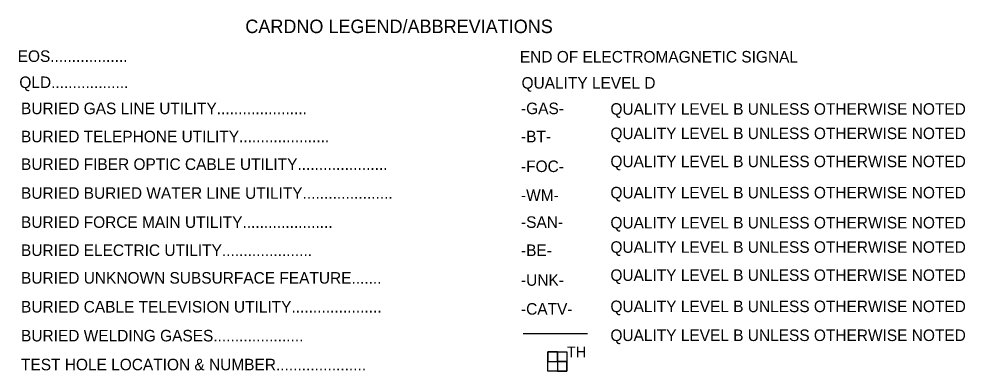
# Model space of a CAD drawing. Extents: x 1797765 to 1816938, y 246120 to 250965.
# Drawn here: x 1805745 to 1806237, y 250781.9 to 250965.2 of the extents above; entities that cross this region are included whole.
import ezdxf

# ---------------------------------------------------------------- set-up
doc = ezdxf.new("R2010")
doc.units = 0
for name, color, linetype in [('EX-UGUT-ELEC-X-CARDNO-X', 7, 'Continuous'), ('EX-UGUT-FOC-X-CARDNO-X', 7, 'Continuous'), ('EX-UGUT-GAS_MAIN-X-CARDNO-X', 7, 'Continuous'), ('EX-UGUT-SANSW-X-CARDNO-X', 7, 'Continuous'), ('EX-UGUT-TELE-X-CARDNO-X', 7, 'Continuous'), ('EX-UGUT-TV-X-CARDNO_X', 7, 'Continuous'), ('EX-UGUT-TXT', 7, 'Continuous'), ('EX-UGUT-WATER-X-CARDNO-X', 7, 'Continuous'), ('EX-UGUT-WEILDING_GAS-X-CARDNO-X', 7, 'Continuous'), ('EX-UGUT-X-CARDNO-X', 7, 'Continuous'), ('SU_QLATestHole_ep', 7, 'Continuous'), ('UGUT-TXT', 7, 'Continuous')]:
    doc.layers.add(name, color=color, linetype=linetype)

msp = doc.modelspace()

# ---------------------------------------------------------------- linework, layer by layer
at = {"layer": 'EX-UGUT-WEILDING_GAS-X-CARDNO-X'}
msp.add_line((1806040.75, 250801.26), (1806007.29, 250801.26), dxfattribs=at)
at = {"layer": 'SU_QLATestHole_ep'}
for p, q in [((1806020.01, 250791.9), (1806030.01, 250791.9)), ((1806020.01, 250781.9), (1806020.01, 250791.9)), ((1806020.01, 250791.9), (1806020.01, 250786.9)), ((1806025.01, 250791.9), (1806020.01, 250791.9)), ((1806025.01, 250791.9), (1806025.01, 250781.9)), ((1806025.01, 250786.9), (1806025.01, 250791.9)), ((1806030.01, 250791.9), (1806030.01, 250781.9)), ((1806020.01, 250786.9), (1806030.01, 250786.9)), ((1806020.01, 250786.9), (1806025.01, 250786.9)), ((1806030.01, 250786.9), (1806025.01, 250786.9)), ((1806025.01, 250786.9), (1806025.01, 250781.9)), ((1806030.01, 250781.9), (1806030.01, 250786.9)), ((1806030.01, 250781.9), (1806020.01, 250781.9)), ((1806025.01, 250781.9), (1806030.01, 250781.9))]:
    msp.add_line(p, q, dxfattribs=at)

# ---------------------------------------------------------------- texts
at = {"layer": 'EX-UGUT-ELEC-X-CARDNO-X'}
msp.add_text('-BE-', height=6.007, dxfattribs=at).set_placement((1806006.12, 250841.81))
at = {"layer": 'EX-UGUT-FOC-X-CARDNO-X'}
msp.add_text('-FOC-', height=6.007, dxfattribs=at).set_placement((1806006.12, 250885.5))
at = {"layer": 'EX-UGUT-GAS_MAIN-X-CARDNO-X'}
msp.add_text('-GAS-', height=6.007, dxfattribs=at).set_placement((1806006.12, 250915.63))
at = {"layer": 'EX-UGUT-SANSW-X-CARDNO-X'}
msp.add_text('-SAN-', height=6.007, dxfattribs=at).set_placement((1806006.12, 250856.44))
at = {"layer": 'EX-UGUT-TELE-X-CARDNO-X'}
msp.add_text('-BT-', height=6.007, dxfattribs=at).set_placement((1806006.12, 250901))
at = {"layer": 'EX-UGUT-TV-X-CARDNO_X'}
msp.add_text('-CATV-', height=6.007, dxfattribs=at).set_placement((1806006.12, 250811.27))
at = {"layer": 'EX-UGUT-TXT'}
for s, p in [('EOS..................', (1805744.38, 250942.82)), ('END OF ELECTROMAGNETIC SIGNAL', (1806005.53, 250942.52)), ('QLD..................', (1805745.25, 250929.23)), ('QUALITY LEVEL D ', (1806006.4, 250928.92)), ('BURIED GAS LINE UTILITY.....................', (1805746.13, 250915.63)), ('QUALITY LEVEL B UNLESS OTHERWISE NOTED', (1806052.61, 250915.33)), ('QUALITY LEVEL B UNLESS OTHERWISE NOTED', (1806052.61, 250902.65)), ('BURIED TELEPHONE UTILITY.....................', (1805746.13, 250901)), ('QUALITY LEVEL B UNLESS OTHERWISE NOTED', (1806052.61, 250888.03)), ('BURIED FIBER OPTIC CABLE UTILITY.....................', (1805746.13, 250886.61)), ('BURIED BURIED WATER LINE UTILITY.....................', (1805746.13, 250871.58)), ('QUALITY LEVEL B UNLESS OTHERWISE NOTED', (1806052.61, 250871.78)), ('BURIED FORCE MAIN UTILITY.....................', (1805746.13, 250856.44)), ('QUALITY LEVEL B UNLESS OTHERWISE NOTED', (1806052.61, 250856.14)), ('QUALITY LEVEL B UNLESS OTHERWISE NOTED', (1806052.61, 250843.46)), ('BURIED ELECTRIC UTILITY.....................', (1805746.13, 250841.81)), ('QUALITY LEVEL B UNLESS OTHERWISE NOTED', (1806052.61, 250828.84)), ('BURIED UNKNOWN SUBSURFACE FEATURE.......', (1805746.13, 250827.42)), ('BURIED CABLE TELEVISION UTILITY.....................', (1805746.13, 250812.39)), ('QUALITY LEVEL B UNLESS OTHERWISE NOTED', (1806052.61, 250812.59)), ('BURIED WELDING GASES.....................', (1805746.13, 250797.35)), ('QUALITY LEVEL B UNLESS OTHERWISE NOTED', (1806052.61, 250797.55)), ('TEST HOLE LOCATION & NUMBER.....................', (1805746.13, 250782.31))]:
    msp.add_text(s, height=6.0075, dxfattribs=at).set_placement(p)
at = {"layer": 'EX-UGUT-WATER-X-CARDNO-X'}
msp.add_text('-WM-', height=6.007, dxfattribs=at).set_placement((1806006.12, 250870.46))
at = {"layer": 'EX-UGUT-X-CARDNO-X'}
msp.add_text('-UNK-', height=6.007, dxfattribs=at).set_placement((1806006.12, 250826.31))
at = {"layer": 'SU_QLATestHole_ep'}
msp.add_text('TH', height=5.6, dxfattribs=at).set_placement((1806030.01, 250789.1))
at = {"layer": 'UGUT-TXT'}
msp.add_text('CARDNO LEGEND/ABBREVIATIONS', height=7.0087, dxfattribs=at).set_placement((1805862.76, 250957.83))

doc.saveas('drawing.dxf')
